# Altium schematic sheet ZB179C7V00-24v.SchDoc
size 1308 x 820 mm
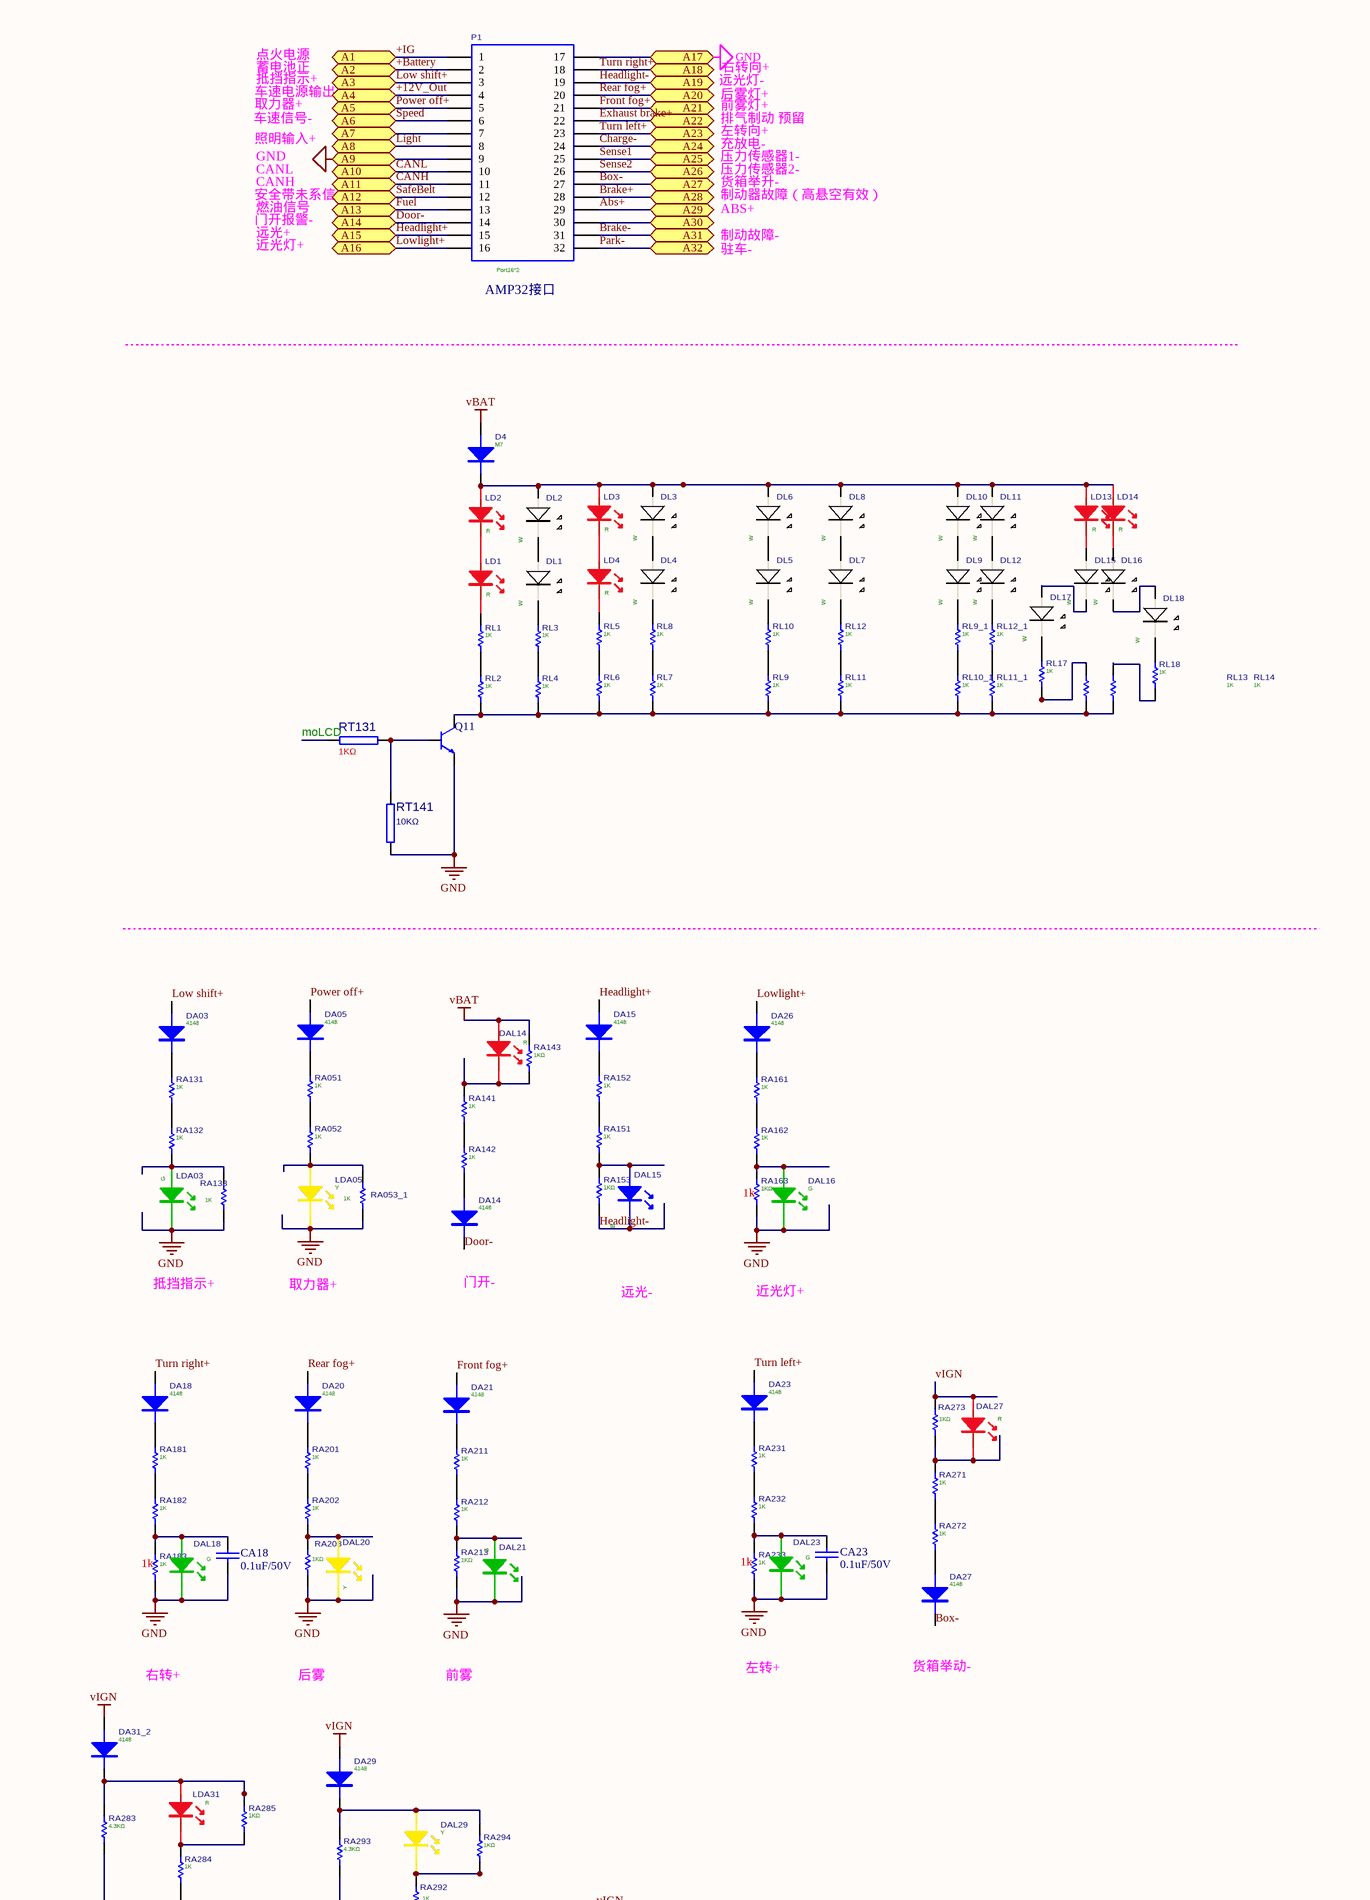
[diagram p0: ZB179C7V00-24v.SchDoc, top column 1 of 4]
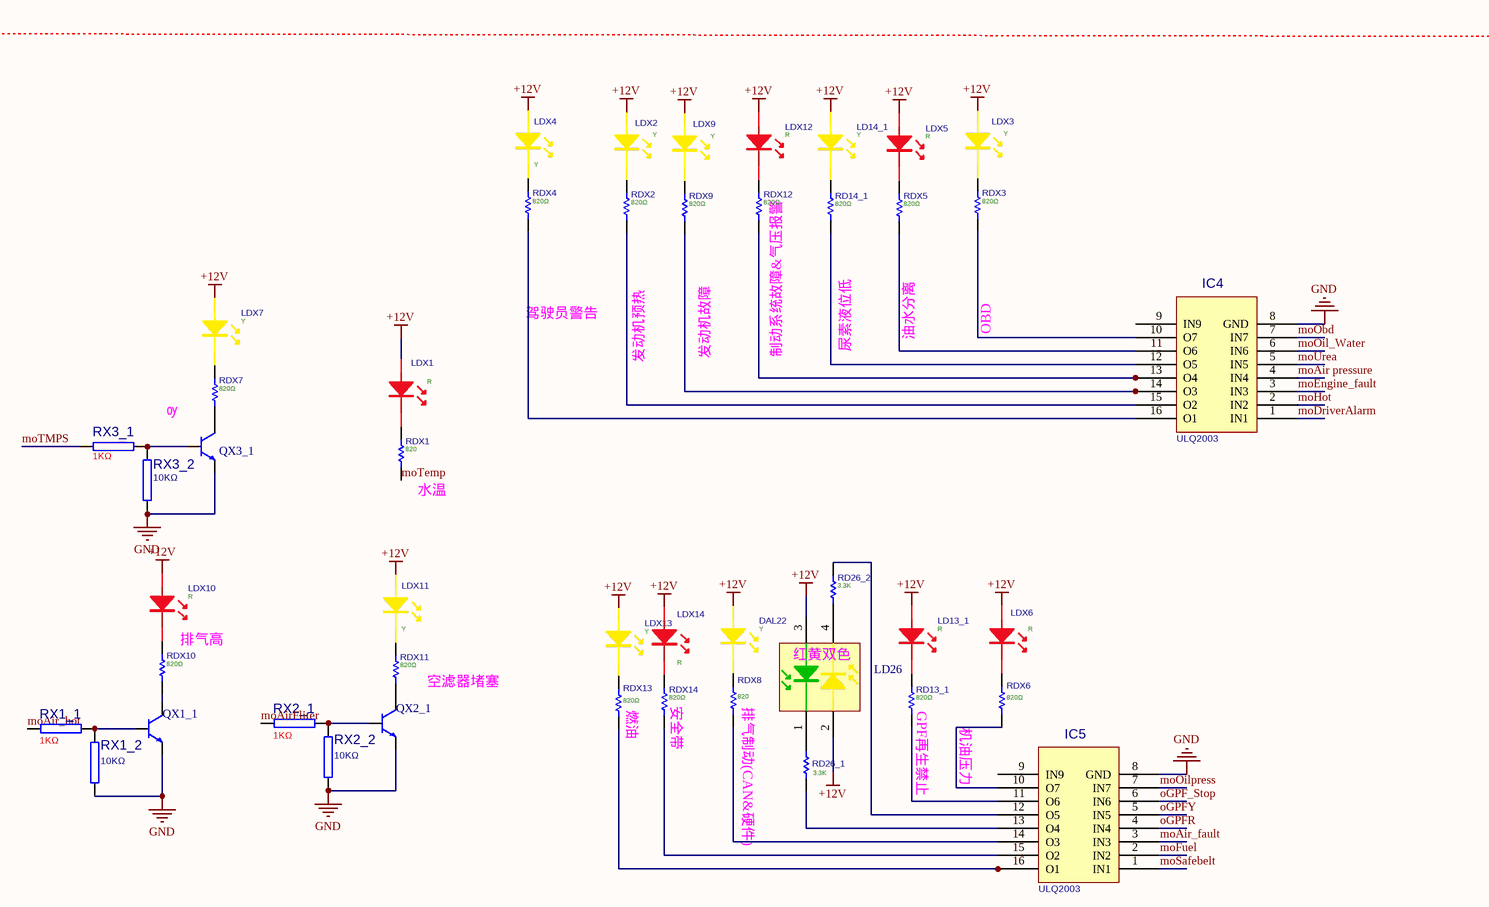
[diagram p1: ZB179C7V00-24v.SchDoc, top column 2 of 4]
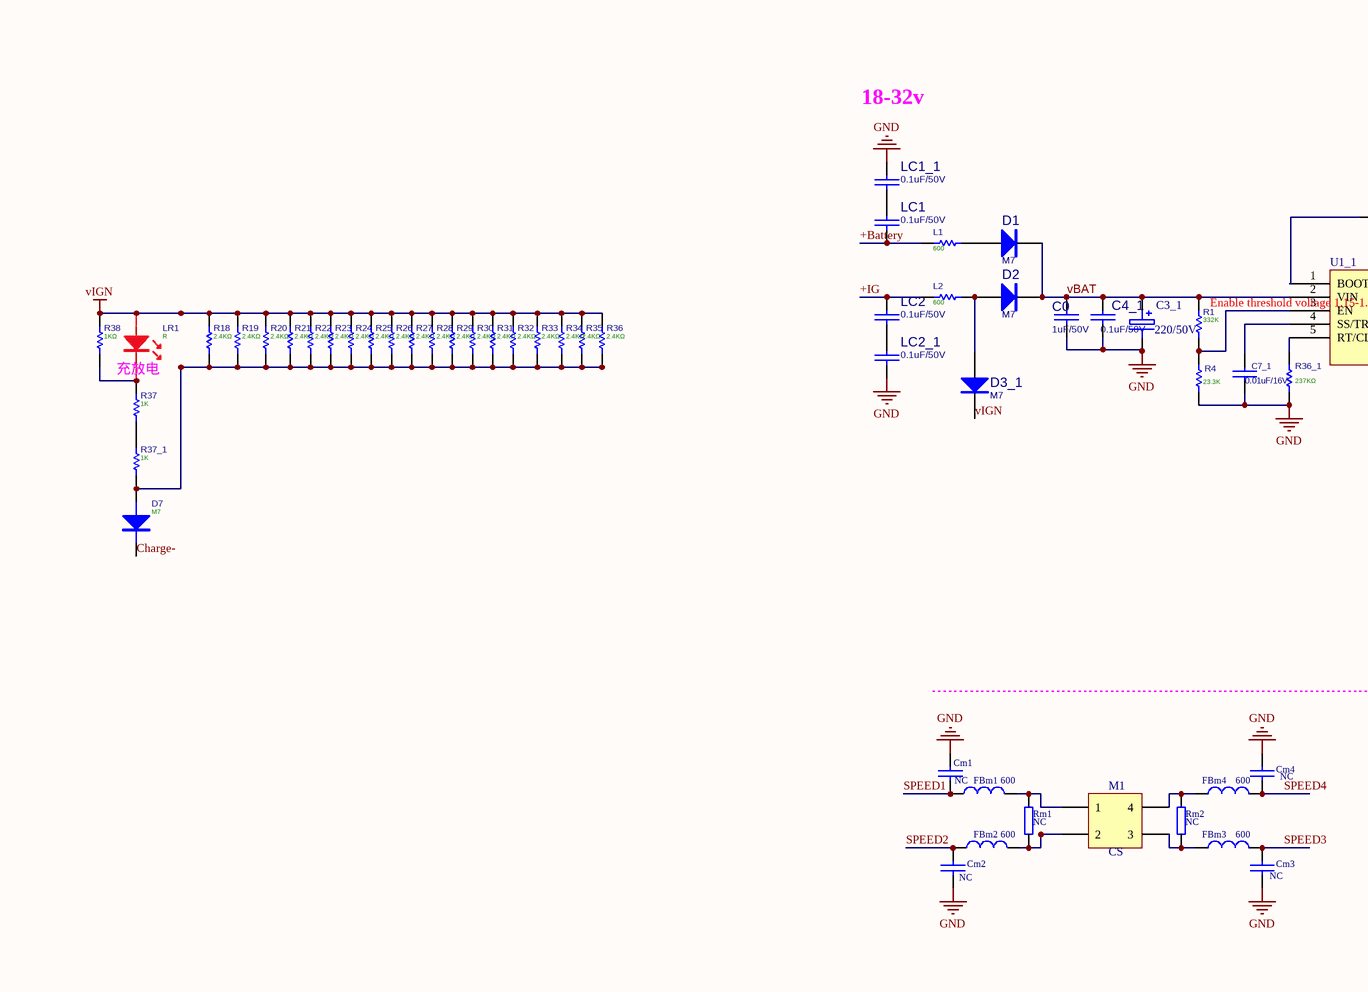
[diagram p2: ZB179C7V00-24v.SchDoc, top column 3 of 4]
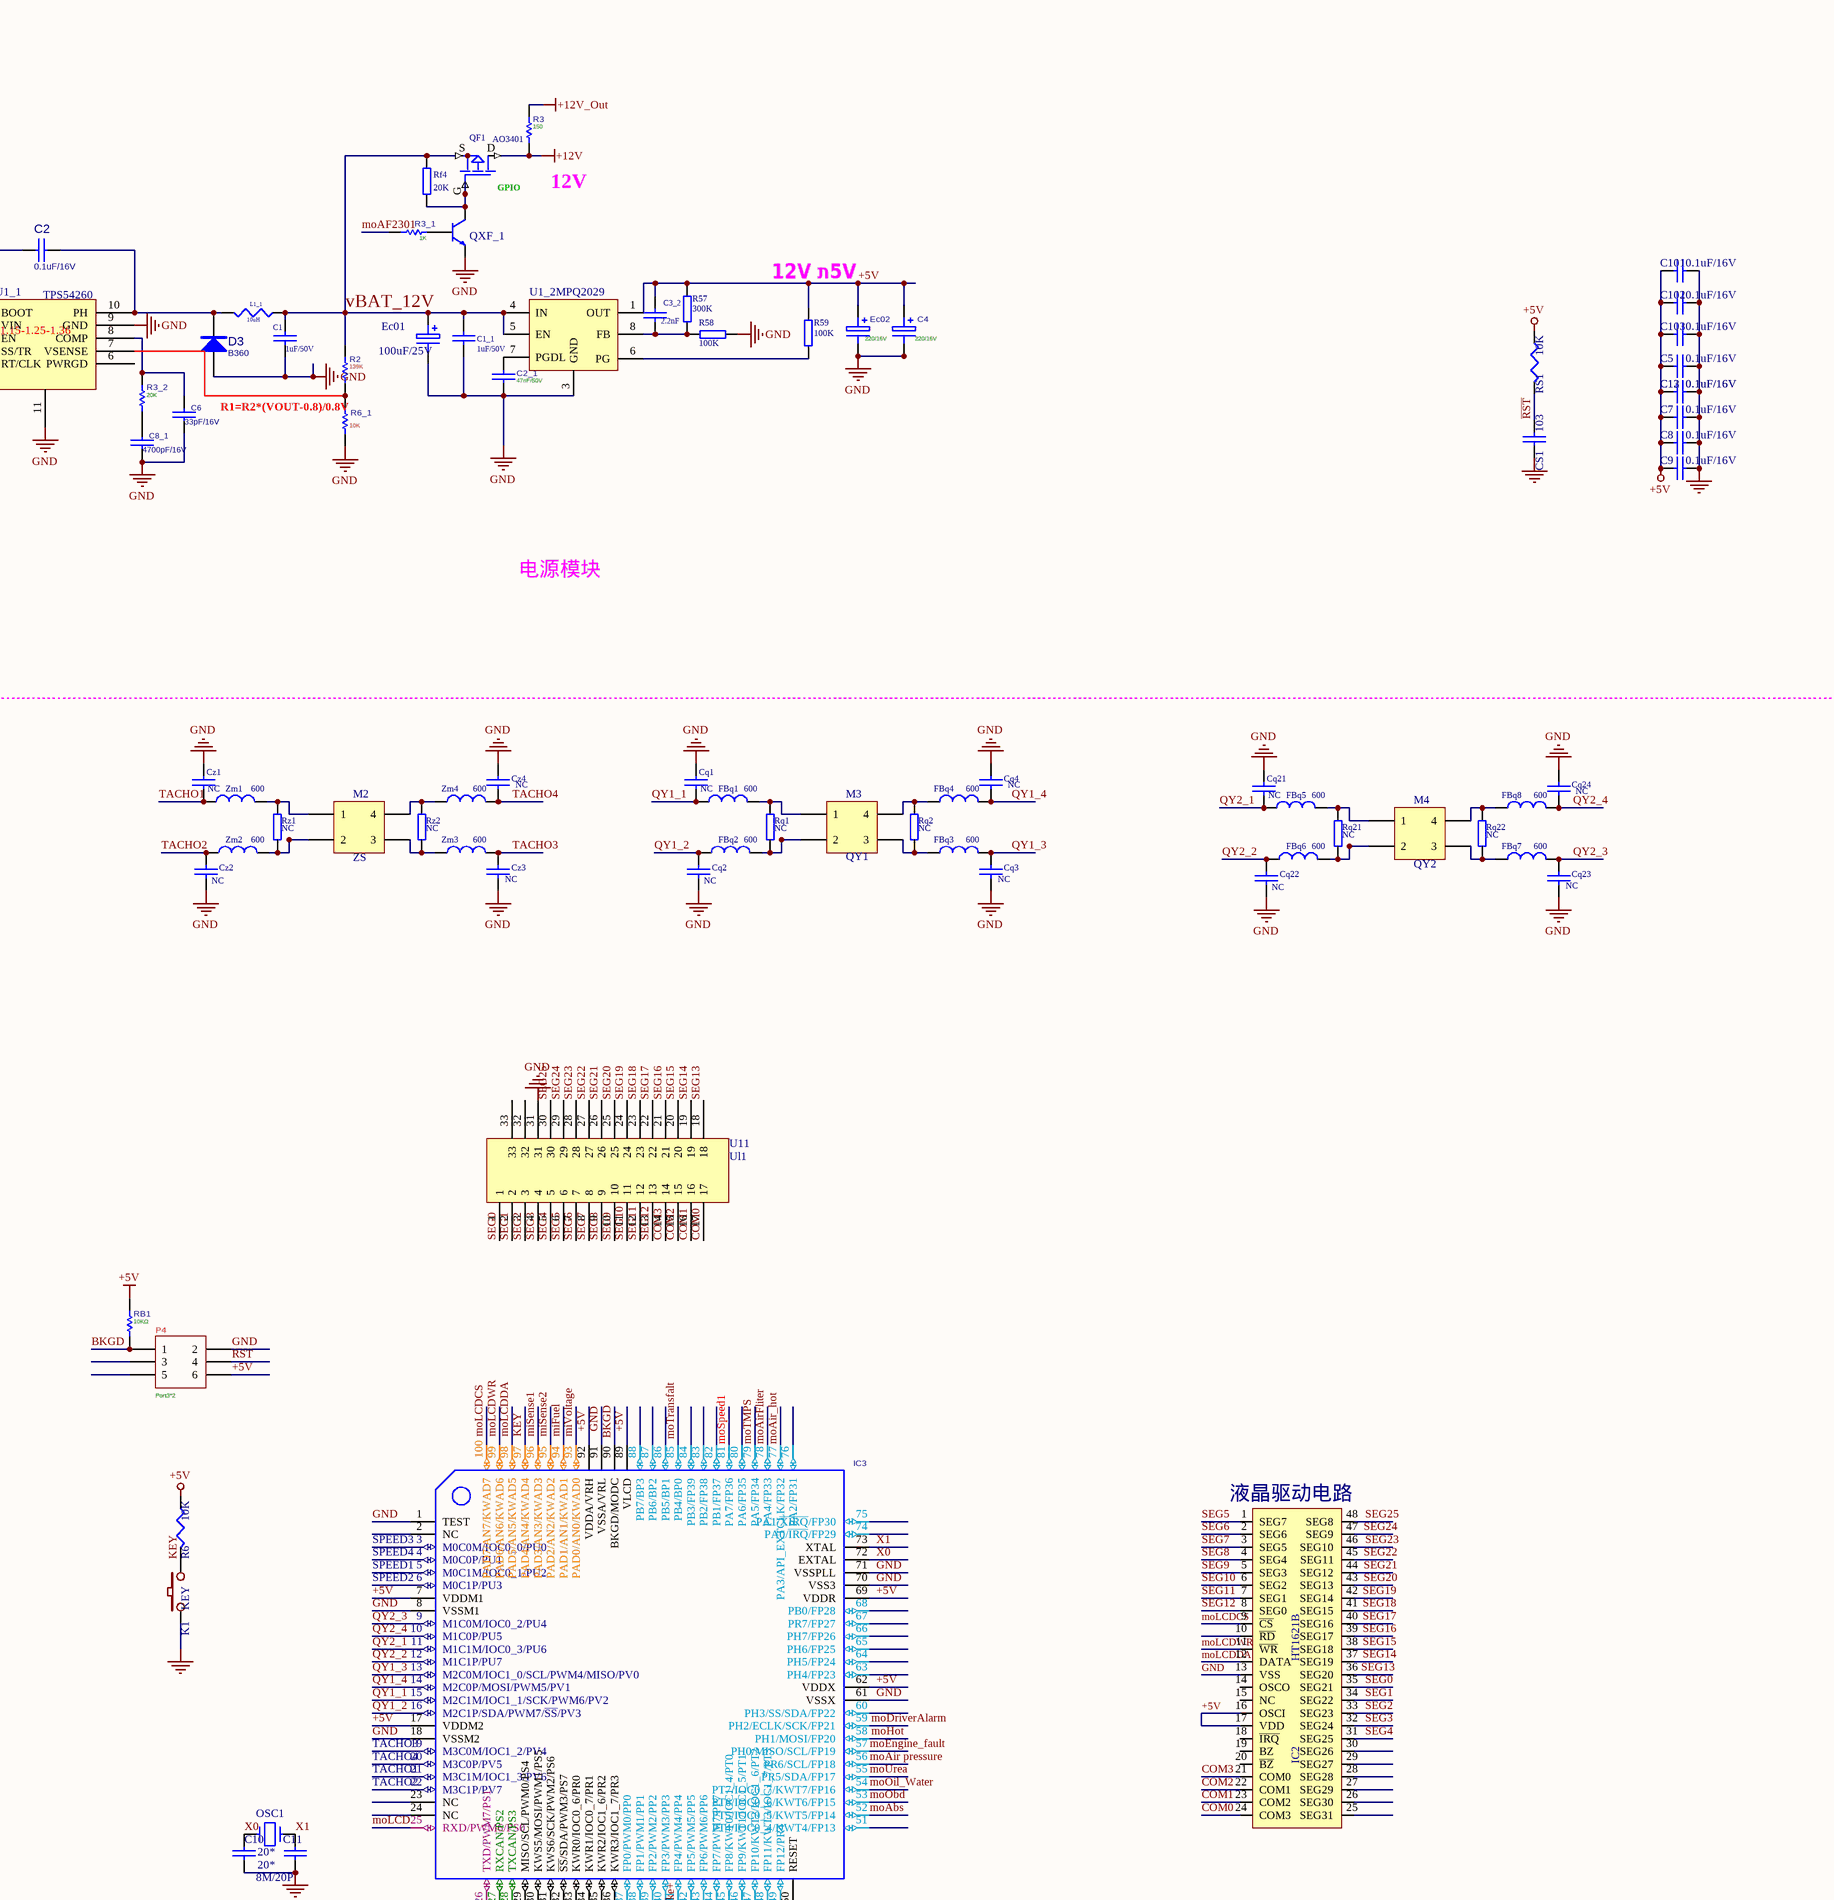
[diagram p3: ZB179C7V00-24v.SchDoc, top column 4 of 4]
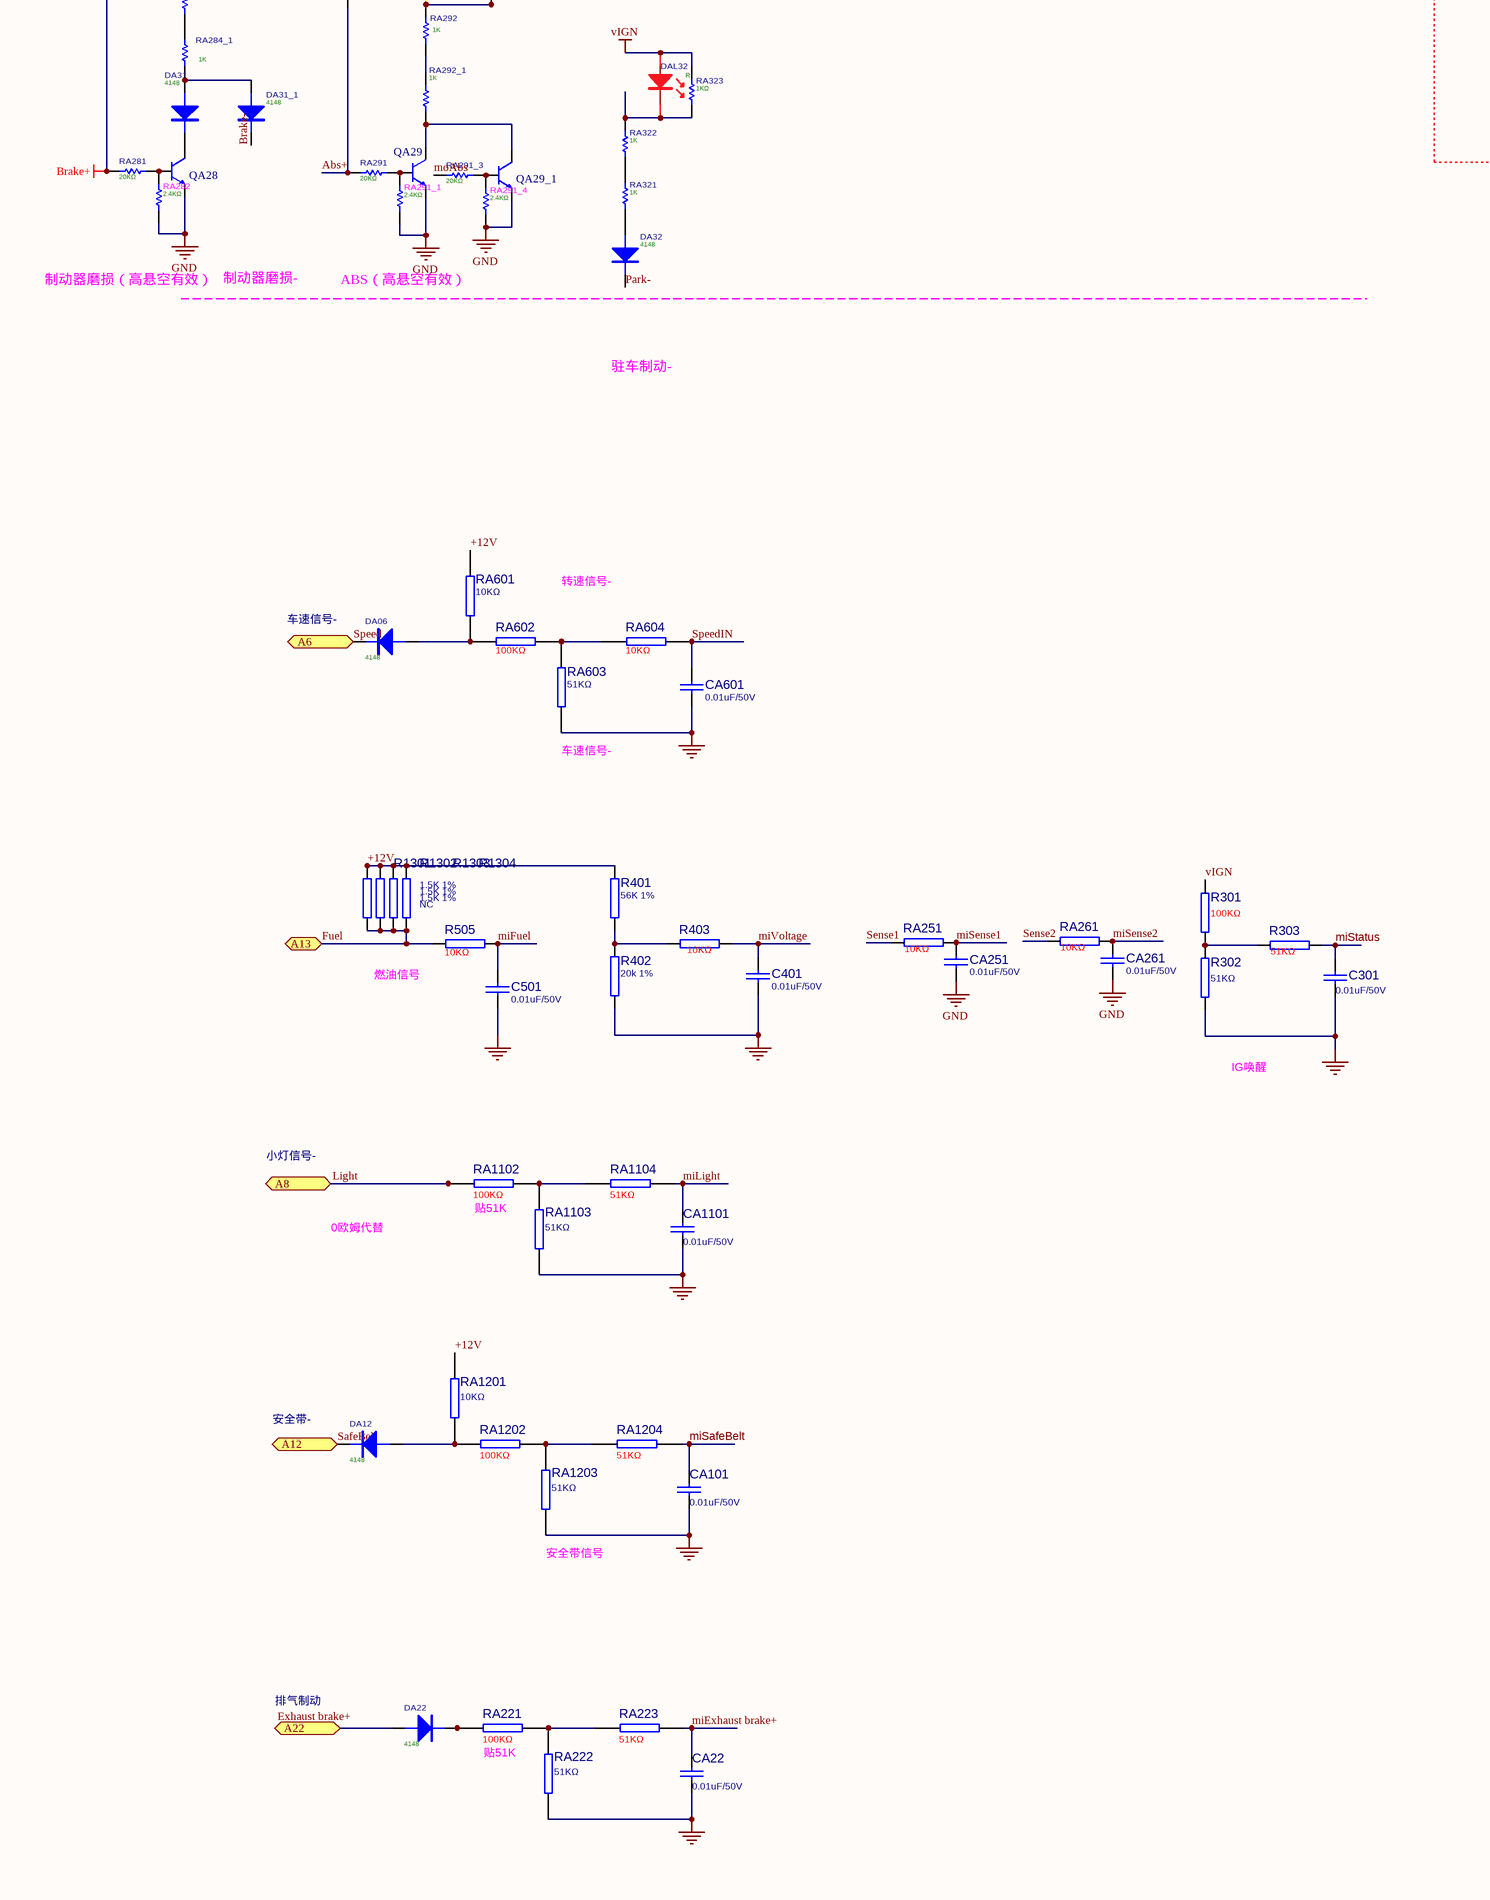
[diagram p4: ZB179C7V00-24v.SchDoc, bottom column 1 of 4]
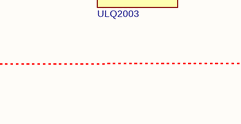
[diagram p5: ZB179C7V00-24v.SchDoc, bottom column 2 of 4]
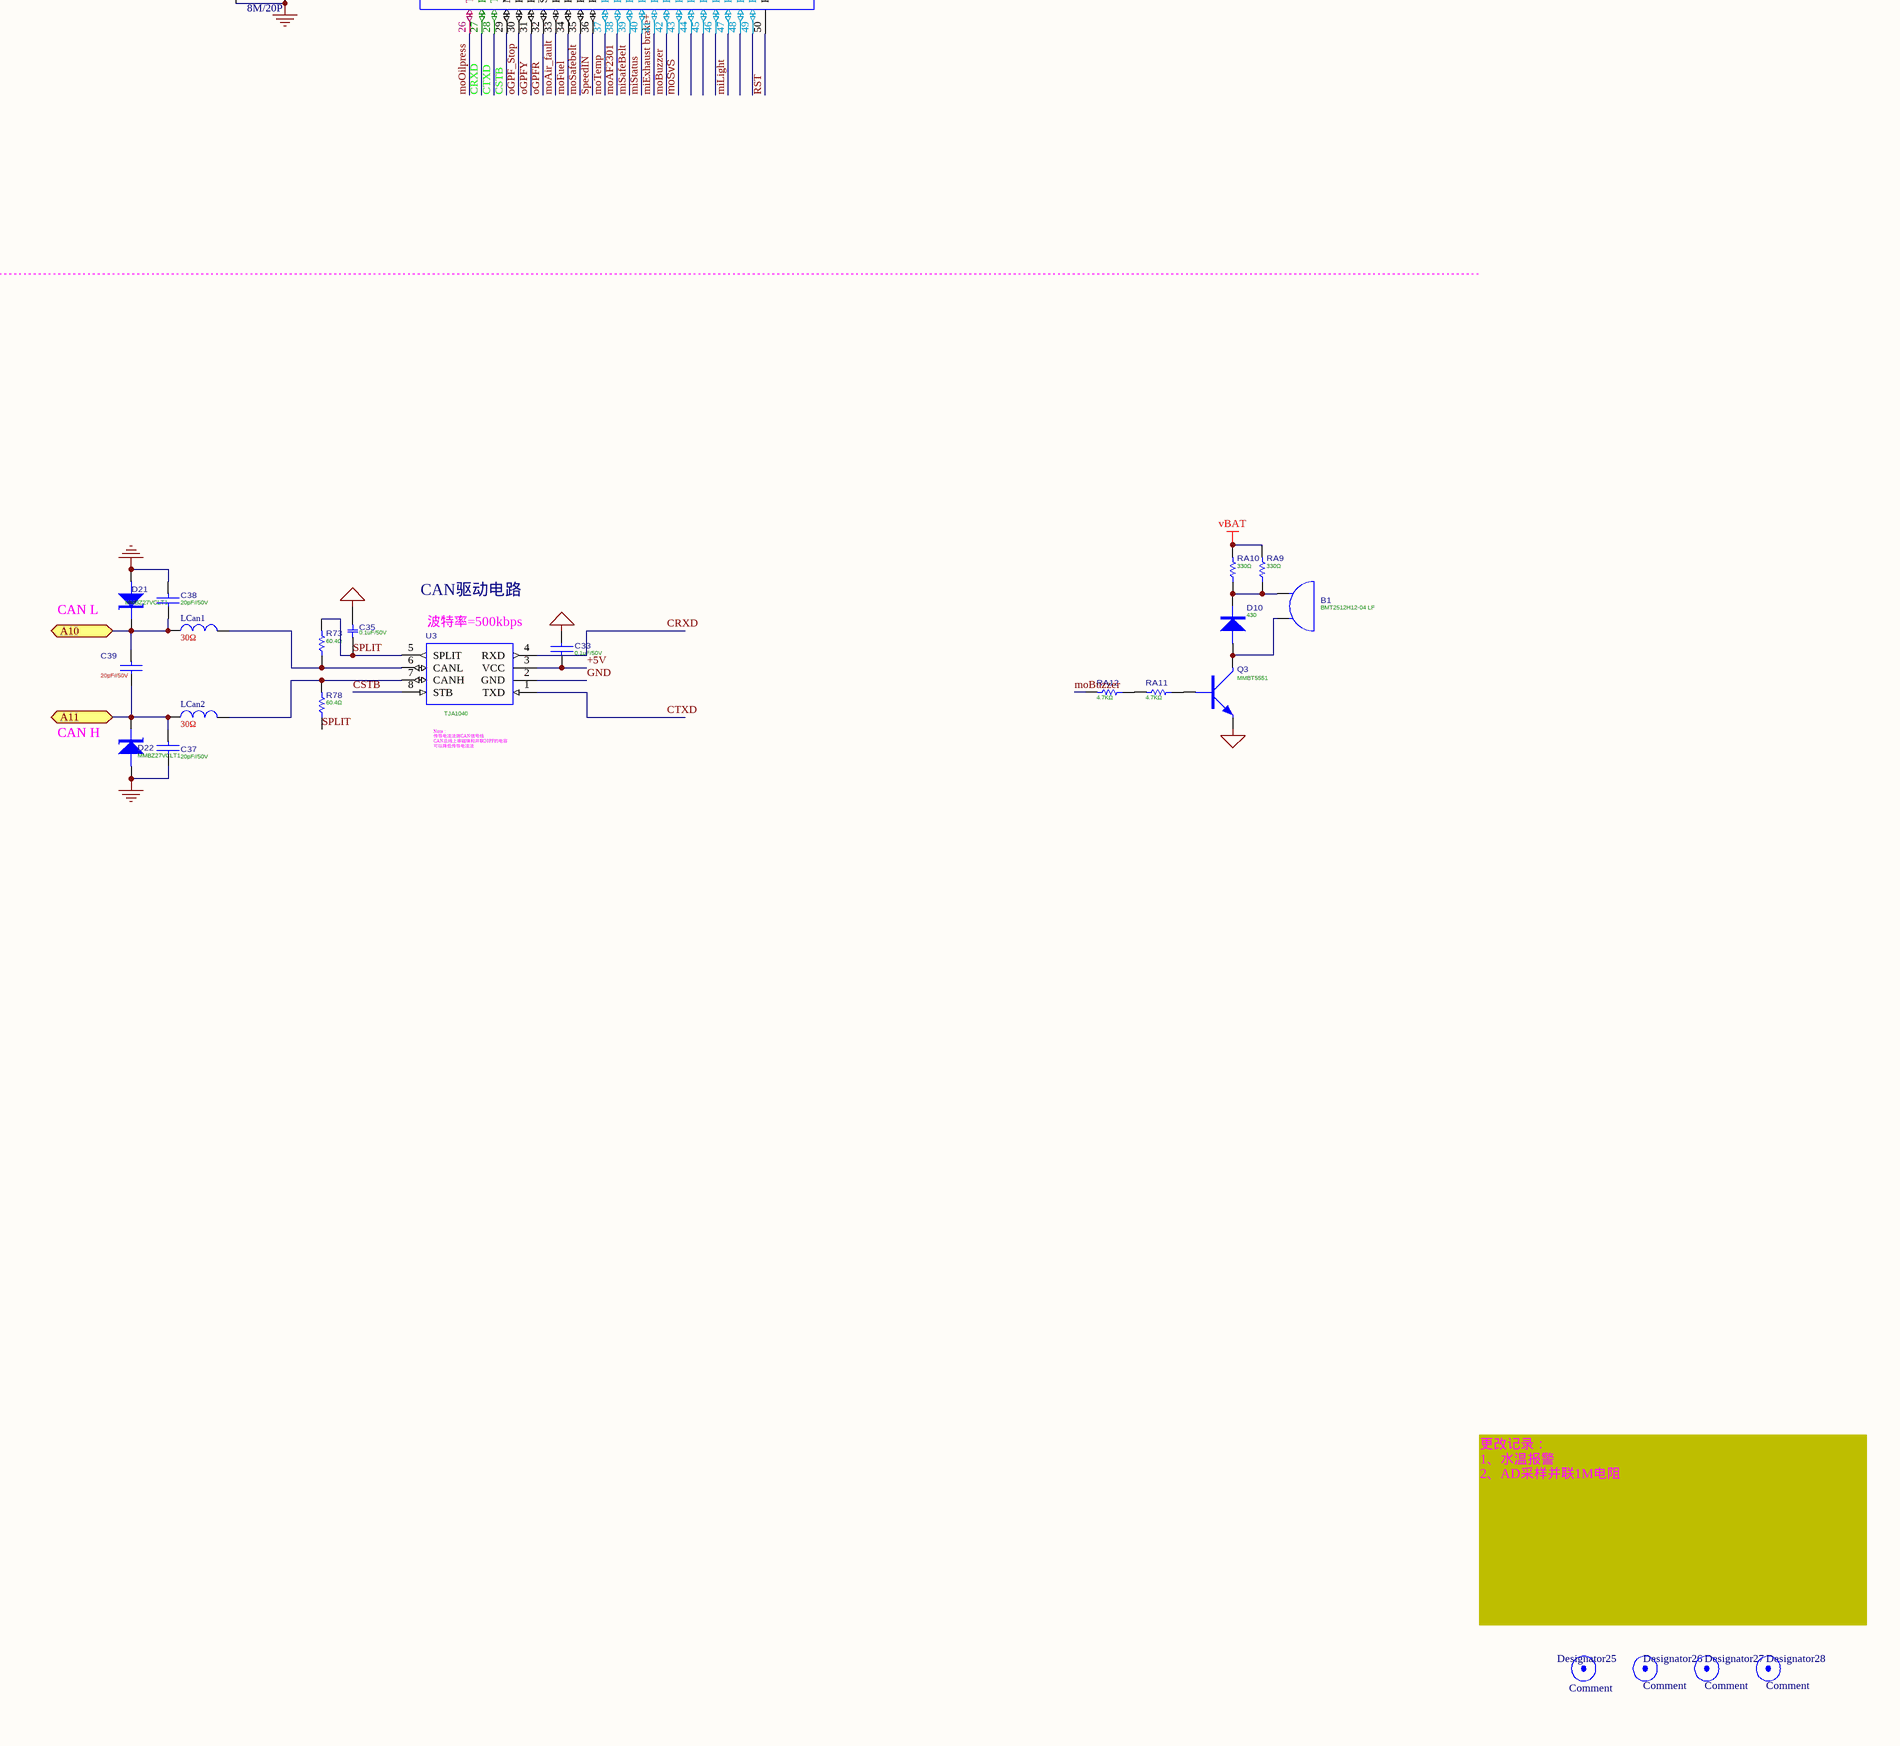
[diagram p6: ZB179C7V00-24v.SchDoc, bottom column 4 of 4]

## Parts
B1  BMT2512H12-04 LF  [AZ-2320E-P1]
C0  1uF/50V  [0805]
C1  1uF/50V  [0805]
C1_1  1uF/50V  [0603]
C2  0.1uF/16V  [0805]
C2_1  47nF/50V  [0603]
C3_1  220/50V  [VZH220/50V]
C3_2  2.2nF  [0603]
C4  220/16V  [VD220/16V]
C4_1  0.1uF/50V  [0805]
C5  0.1uF/16V  [0603]
C6  33pF/16V  [0603]
C7  0.1uF/16V  [0603]
C7_1  0.01uF/16V  [0603]
C8  0.1uF/16V  [0603]
C8_1  4700pF/16V  [0805]
C9  0.1uF/16V  [0603]
C10  20*  [0603]
C11  20*  [0603]
C12  0.1uF/16V  [0603]
C13  0.1uF/16V  [0603]
C33  0.1uF/50V  [0603]
C35  0.1uF/50V  [0603]
C37  20pF//50V  [0603]
C38  20pF//50V  [0603]
C39  20pF//50V  [0603]
C101  0.1uF/16V  [0603]
C102  0.1uF/16V  [0603]
C103  0.1uF/16V  [0603]
C301  0.01uF/50V  [0603]
C401  0.01uF/50V  [0603]
C501  0.01uF/50V  [0603]
CA18  0.1uF/50V  [0805]
CA22  0.01uF/50V  [0603]
CA23  0.1uF/50V  [0805]
CA101  0.01uF/50V  [0603]
CA251  0.01uF/50V  [0603]
CA261  0.01uF/50V  [0603]
CA601  0.01uF/50V  [C0603]
CA1101  0.01uF/50V  [0603]
Cm1  NC  [0603]
Cm2  NC  [0603]
Cm3  NC  [0603]
Cm4  NC  [0603]
Cq1  NC  [0603]
Cq2  NC  [0603]
Cq3  NC  [0603]
Cq4  NC  [0603]
Cq21  NC  [0603]
Cq22  NC  [0603]
Cq23  NC  [0603]
Cq24  NC  [0603]
CS1  103  [0603]
Cz1  NC  [0603]
Cz2  NC  [0603]
Cz3  NC  [0603]
Cz4  NC  [0603]
D1  M7  [7227]
D2  M7  [7227]
D3  B360  [7227]
D3_1  M7  [7227]
D4  M7  [7227]
D7  M7  [7227]
D10  430  [MiniMELF/SOD-80C]
D21  MMBZ27VCLT1  [SOT-23-BEC]
D22  MMBZ27VCLT1  [SOT-23-BEC]
DA03  4148  [MiniMELF/SOD-80C]
DA05  4148  [MiniMELF/SOD-80C]
DA06  4148  [MiniMELF/SOD-80C]
DA12  4148  [MiniMELF/SOD-80C]
DA14  4148  [MiniMELF/SOD-80C]
DA15  4148  [MiniMELF/SOD-80C]
DA18  4148  [MiniMELF/SOD-80C]
DA20  4148  [MiniMELF/SOD-80C]
DA21  4148  [MiniMELF/SOD-80C]
DA22  4148  [MiniMELF/SOD-80C]
DA23  4148  [MiniMELF/SOD-80C]
DA26  4148  [MiniMELF/SOD-80C]
DA27  4148  [MiniMELF/SOD-80C]
DA29  4148  [MiniMELF/SOD-80C]
DA31  4148  [MiniMELF/SOD-80C]
DA31_1  4148  [MiniMELF/SOD-80C]
DA31_2  4148  [MiniMELF/SOD-80C]
DA32  4148  [MiniMELF/SOD-80C]
DAL14  R  [LED3528]
DAL15  B  [LED3528]
DAL16  G  [LED3528]
DAL18  G  [LED3528]
DAL20  Y  [LED3528]
DAL21  G  [LED3528]
DAL22  Y  [LED3528]
DAL23  G  [LED3528]
DAL27  R  [LED3528]
DAL29  Y  [LED3528]
DAL32  R  [LED3528]
Designator25  Comment  [MARK]
Designator26  Comment  [MARK]
Designator27  Comment  [MARK]
Designator28  Comment  [MARK]
DL1  W  [LED3528]
DL2  W  [LED3528]
DL3  W  [LED3528]
DL4  W  [LED3528]
DL5  W  [LED3528]
DL6  W  [LED3528]
DL7  W  [LED3528]
DL8  W  [LED3528]
DL9  W  [LED3528]
DL10  W  [LED3528]
DL11  W  [LED3528]
DL12  W  [LED3528]
DL15  W  [LED3528]
DL16  W  [LED3528]
DL17  W  [LED3528]
DL18  W  [LED3528]
Ec01  100uF/25V  [4E220/16H]
Ec02  220/16V  [VD220/16V]
FBm1  600  [0603]
FBm2  600  [0603]
FBm3  600  [0603]
FBm4  600  [0603]
FBq1  600  [0603]
FBq2  600  [0603]
FBq3  600  [0603]
FBq4  600  [0603]
FBq5  600  [0603]
FBq6  600  [0603]
FBq7  600  [0603]
FBq8  600  [0603]
IC2  HT1621B  [SSO-48]
IC3  MC9S12HY48MLL  [TQFP-100-0.5]  (value not drawn)
IC4  ULQ2003  [SO-16]
IC5  ULQ2003  [SO-16]
K1  KEY  [K1]
L1  600  [0805]
L1_1  10uH  [SPM6530T-100M]
L2  600  [0805]
LC1  0.1uF/50V  [0805]
LC1_1  0.1uF/50V  [0805]
LC2  0.1uF/50V  [0805]
LC2_1  0.1uF/50V  [0805]
LCan1  30Ω  [0603]
LCan2  30Ω  [0603]
LD1  R  [LED3528]
LD2  R  [LED3528]
LD3  R  [LED3528]
LD4  R  [LED3528]
LD13  R  [LED3528]
LD13_1  R  [LED3528]
LD14  R  [LED3528]
LD14_1  Y  [LED3528]
LD26  Y/G  [67-22]  (value not drawn)
LDA03  G  [LED3528]
LDA05  Y  [LED3528]
LDA31  R  [LED3528]
LDX1  R  [LED3528]
LDX2  Y  [LED3528]
LDX3  Y  [LED3528]
LDX4  Y  [LED3528]
LDX5  R  [LED3528]
LDX6  R  [LED3528]
LDX7  Y  [LED3528]
LDX9  Y  [LED3528]
LDX10  R  [LED3528]
LDX11  Y  [LED3528]
LDX12  R  [LED3528]
LDX13  Y  [LED3528]
LDX14  R  [LED3528]
LR1  R  [LED3528]
M1  CS  [M]
M2  ZS  [M]
M3  QY1  [M]
M4  QY2  [M]
OSC1  8M/20P  [HC-49S]
P1  Port16*2  [AMP-32-B]
P4  Port3*2  [SIP-6]
Q3  MMBT5551  [SOT-23-BEC]
Q11  5551  [SOT-23-BEC]  (value not drawn)
QA28  5551  [SOT-23-BEC]  (value not drawn)
QA29  5551  [SOT-23-BEC]  (value not drawn)
QA29_1  5551  [SOT-23-BEC]  (value not drawn)
QF1  AO3401  [SOT-23-GSD]
QX1_1  5551  [SOT-23-BEC]  (value not drawn)
QX2_1  5551  [SOT-23-BEC]  (value not drawn)
QX3_1  5551  [SOT-23-BEC]  (value not drawn)
QXF_1  5551  [SOT-23-BEC]  (value not drawn)
R1  332K  [0603]
R2  139K  [1206]
R3  150  [1206]
R3_1  1K  [0603]
R3_2  20K  [0603]
R4  23.3K  [0603]
R6  10K  [0603]
R6_1  10K  [1206]
R18  2.4KΩ  [1206]
R19  2.4KΩ  [1206]
R20  2.4KΩ  [1206]
R21  2.4KΩ  [1206]
R22  2.4KΩ  [1206]
R23  2.4KΩ  [1206]
R24  2.4KΩ  [1206]
R25  2.4KΩ  [1206]
R26  2.4KΩ  [1206]
R27  2.4KΩ  [1206]
R28  2.4KΩ  [1206]
R29  2.4KΩ  [1206]
R30  2.4KΩ  [1206]
R31  2.4KΩ  [1206]
R32  2.4KΩ  [1206]
R33  2.4KΩ  [1206]
R34  2.4KΩ  [1206]
R35  2.4KΩ  [1206]
R36  2.4KΩ  [1206]
R36_1  237KΩ  [0603]
R37  1K  [1206]
R37_1  1K  [1206]
R38  1KΩ  [0603]
R57  300K  [0603]
R58  100K  [0603]
R59  100K  [0603]
R73  60.4Ω  [1206]
R78  60.4Ω  [1206]
R301  100KΩ  [0603]
R302  51KΩ  [0603]
R303  51KΩ  [0603]
R401  56K 1%  [0805]
R402  20k 1%  [0805]
R403  10KΩ  [0805]
R505  10KΩ  [1206]
R1301  1.5K 1%  [1206]
R1302  1.5K 1%  [1206]
R1303  NC  [1206]
R1304  1.5K 1%  [1206]
RA9  330Ω  [1206]
RA10  330Ω  [1206]
RA11  4.7KΩ  [0603]
RA12  4.7KΩ  [0603]
RA051  1K  [1206]
RA052  1K  [1206]
RA053_1  1K  [0805]
RA131  1K  [1206]
RA132  1K  [1206]
RA133  1K  [0805]
RA141  1K  [1206]
RA142  1K  [1206]
RA143  1KΩ  [0805]
RA151  1K  [1206]
RA152  1K  [1206]
RA153  1KΩ  [0805]
RA161  1K  [1206]
RA162  1K  [1206]
RA163  1KΩ  [0805]
RA181  1K  [1206]
RA182  1K  [1206]
RA183  1K  [0805]
RA201  1K  [1206]
RA202  1K  [1206]
RA203  1KΩ  [0805]
RA211  1K  [1206]
RA212  1K  [1206]
RA213  1KΩ  [0805]
RA221  100KΩ  [0805]
RA222  51KΩ  [0805]
RA223  51KΩ  [0805]
RA231  1K  [1206]
RA232  1K  [1206]
RA233  1K  [0805]
RA251  10KΩ  [0805]
RA261  10KΩ  [0805]
RA271  1K  [1206]
RA272  1K  [1206]
RA273  1KΩ  [0805]
RA281  20KΩ  [0603]
RA282  2.4KΩ  [0603]
RA283  4.3KΩ  [0603]
RA284  1K  [1206]
RA284_1  1K  [1206]
RA285  1KΩ  [0805]
RA291  20KΩ  [0603]
RA291_1  2.4KΩ  [0603]
RA291_3  20KΩ  [0603]
RA291_4  2.4KΩ  [0603]
RA292  1K  [1206]
RA292_1  1K  [1206]
RA293  4.3KΩ  [0805]
RA294  1KΩ  [0805]
RA321  1K  [1206]
RA322  1K  [1206]
RA323  1KΩ  [0805]
RA601  10KΩ  [0805]
RA602  100KΩ  [0805]
RA603  51KΩ  [0805]
RA604  10KΩ  [0805]
RA1102  100KΩ  [0603]
RA1103  51KΩ  [0603]
RA1104  51KΩ  [0603]
RA1201  10KΩ  [0805]
RA1202  100KΩ  [0805]
RA1203  51KΩ  [0805]
RA1204  51KΩ  [0805]
RB1  10KΩ  [0603]
RD13_1  820Ω  [1206]
RD14_1  820Ω  [1206]
RD26_1  3.3K  [1206]
RD26_2  3.3K  [1206]
RDX1  820  [1206]
RDX2  820Ω  [1206]
RDX3  820Ω  [1206]
RDX4  820Ω  [1206]
RDX5  820Ω  [1206]
RDX6  820Ω  [1206]
RDX7  820Ω  [1206]
RDX8  820  [1206]
RDX9  820Ω  [1206]
RDX10  820Ω  [1206]
RDX11  820Ω  [1206]
RDX12  820Ω  [1206]
RDX13  820Ω  [1206]
RDX14  820Ω  [1206]
Rf4  20K  [0603]
RL1  1K  [1206]
RL2  1K  [1206]
RL3  1K  [1206]
RL4  1K  [1206]
RL5  1K  [1206]
RL6  1K  [1206]
RL7  1K  [1206]
RL8  1K  [1206]
RL9  1K  [1206]
RL9_1  1K  [1206]
RL10  1K  [1206]
RL10_1  1K  [1206]
RL11  1K  [1206]
RL11_1  1K  [1206]
RL12  1K  [1206]
RL12_1  1K  [1206]
RL13  1K  [1206]
RL14  1K  [1206]
RL17  1K  [1206]
RL18  1K  [1206]
Rm1  NC  [0603]
Rm2  NC  [0603]
Rq1  NC  [0603]
Rq2  NC  [0603]
Rq21  NC  [0603]
Rq22  NC  [0603]
RS1  10K  [0603]
RT131  1KΩ  [0603]
RT141  10KΩ  [0603]
RX1_1  1KΩ  [0603]
RX1_2  10KΩ  [0603]
RX2_1  1KΩ  [0603]
RX2_2  10KΩ  [0603]
RX3_1  1KΩ  [0603]
RX3_2  10KΩ  [0603]
Rz1  NC  [0603]
Rz2  NC  [0603]
U1_1  TPS54260  [MSOP]
U1_2  MPQ2029  [SOIC8]
U3  TJA1040  [SO-8]
U11  Ul1  [LCD]
Zm1  600  [0603]
Zm2  600  [0603]
Zm3  600  [0603]
Zm4  600  [0603]

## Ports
A1, A2, A3, A4, A5, A6, A7, A8, A9, A10, A11, A12, A13, A14, A15, A16, A17, A18, A19, A20, A21, A22, A23, A24, A25, A26, A27, A28, A29, A30, A31, A32

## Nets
+5V: C3_2.1 C4.+ C5.2 C7.2 C8.2 C9.2 C12.2 C13.2 C33.1 C101.2 C102.2 C103.2 Ec02.+ IC2.16(OSCI) IC2.17(VDD) IC3.7(VDDM1) IC3.17(VDDM2) IC3.62(VDDX) IC3.69(VDDR) IC3.89(VLCD) IC3.92(VDDA/VRH) P4.6 R6.2 R57.2 R59.2 RB1.2 RS1.2 U1_2.1(OUT) U3.3(VCC)
+12V: DAL22.1 LD13_1.1 LD14_1.1 LD26.2 LD26.3 LDX1.1 LDX2.1 LDX3.1 LDX4.1 LDX5.1 LDX6.1 LDX7.1 LDX9.1 LDX10.1 LDX11.1 LDX12.1 LDX13.1 LDX14.1 QF1.D R3.1 R401.2 R1301.2 R1302.2 R1303.2 R1304.2 RA601.1 RA1201.2
+12V_Out: P1.4 R3.2 ; port A4
Brake+: P1.28 RA281.1 RA283.1 ; port A28
GND: C0.2 C1.2 C1_1.2 C2_1.1 C3_1.- C4.- C4_1.2 C5.1 C6.1 C7.1 C7_1.1 C8.1 C8_1.1 C9.1 C10.2 C11.2 C12.1 C13.1 C33.2 C35.2 C37.2 C38.1 C101.1 C102.1 C103.1 C301.1 C401.2 C501.2 CA18.2 CA22.2 CA23.2 CA101.2 CA251.2 CA261.2 CA601.1 CA1101.2 Cm1.1 Cm2.2 Cm3.2 Cm4.1 Cq1.1 Cq2.2 Cq3.2 Cq4.1 Cq21.1 Cq22.2 Cq23.2 Cq24.1 CS1.1 Cz1.1 Cz2.2 Cz3.2 Cz4.1 D3.1 D21.1 D22.1 DAL16.2 DAL18.2 DAL20.2 DAL21.2 DAL23.2 Ec01.2 Ec02.- IC2.13(VSS) IC3.1(TEST) IC3.8(VSSM1) IC3.18(VSSM2) IC3.61(VSSX) IC3.70(VSS3) IC3.71(VSSPLL) IC3.91(VSSA/VRL) IC4.8(GND) IC5.8(GND) K1.1 LC1_1.1 LC2_1.2 LDA03.2 LDA05.2 P1.9 P1.17 P4.2 Q3.E Q11.E QA28.E QA29.E QA29_1.E QX1_1.E QX2_1.E QX3_1.E QXF_1.E R4.1 R6_1.1 R36_1.1 R58.2 R302.2 R402.2 RA053_1.2 RA133.2 RA163.1 RA183.1 RA203.2 RA213.2 RA222.1 RA233.1 RA282.1 RA291_1.1 RA291_4.1 RA603.2 RA1103.1 RA1203.1 RT141.2 RX1_2.2 RX2_2.2 RX3_2.2 U1_1.9(GND) U1_1.11 U1_2.3(GND) U3.2(GND) U11.31 ; port A9, port A17
vBAT: C0.1 C3_1.+ C4_1.1 D1.2 D2.2 D4.1 DAL14.1 R1.2 RA9.2 RA10.2 RA143.2 U1_1.2(VIN)
vIGN: D3_1.2 DA29.1 DA31_2.1 DAL27.1 DAL32.1 LR1.1 R18.2 R19.2 R20.2 R21.2 R22.2 R23.2 R24.2 R25.2 R26.2 R27.2 R28.2 R29.2 R30.2 R31.2 R32.2 R33.2 R34.2 R35.2 R36.2 R38.2 R301.1 RA273.1 RA323.2
+Battery: L1.2 LC1.2 P1.2 ; port A2
+IG: L2.2 LC2.1 P1.1 ; port A1
A7: P1.7 ; port A7
A30: P1.30 ; port A30
Abs+: P1.29 RA291.1 RA293.1 ; port A29
BKGD: IC3.90(BKGD/MODC) P4.1 RB1.1
Box-: DA27.2 P1.27 ; port A27
Brake-: DA31_1.2 P1.31 ; port A31
CANH: C37.1 C39.2 D22.2 LCan2.2 P1.11 ; port A11
CANL: C38.2 C39.1 D21.2 LCan1.2 P1.10 ; port A10
Charge-: D7.2 P1.24 ; port A24
COM0: IC2.24(COM3) U11.17
COM1: IC2.23(COM2) U11.16
COM2: IC2.22(COM1) U11.15
COM3: IC2.21(COM0) U11.14
CRXD: IC3.27(RXCAN/PS2) U3.4(RXD)
CSTB: IC3.29(MISO/SCL/PWM0/PS4) U3.8(STB)
CTXD: IC3.28(TXCAN/PS3) U3.1(TXD)
Door-: DA14.2 P1.14 ; port A14
Exhaust brake+: DA22.1 P1.22 ; port A22
Front fog+: DA21.1 P1.21 ; port A21
Fuel: P1.13 R505.2 R1301.1 R1302.1 R1303.1 R1304.1 ; port A13
Headlight+: DA15.1 P1.15 ; port A15
Headlight-: DAL15.2 P1.19 RA153.2 ; port A19
KEY: IC3.97(PAD4/AN4/KWAD4) K1.2 R6.1
Light: P1.8 RA1102.2 ; port A8
Low shift+: DA03.1 P1.3 ; port A3
Lowlight+: DA26.1 P1.16 ; port A16
miExhaust brake+: CA22.1 IC3.41(FP4/PWM4/PP4) RA223.2
miFuel: C501.1 IC3.94(PAD1/AN1/KWAD1) R505.1
miLight: CA1101.1 IC3.47(FP10/KWT2/IOC1_6/PT2) RA1104.2
miSafeBelt: CA101.1 IC3.39(FP2/PWM2/PP2) RA1204.2
miSense1: CA251.1 IC3.96(PAD3/AN3/KWAD3) RA251.1
miSense2: CA261.1 IC3.95(PAD2/AN2/KWAD2) RA261.1
miStatus: C301.2 IC3.40(FP3/PWM3/PP3) R303.1
miVoltage: C401.1 IC3.93(PAD0/AN0/KWAD0) R403.1
moAbs: IC3.52(PT5/IOC0_5/KWT5/FP14) RA291_3.1
moAF2301: IC3.38(FP1/PWM1/PP1) R3_1.2
moAir pressure: IC3.56(PR6/SCL/FP18) IC4.4(IN4)
moAir_fault: IC3.33(KWR0/IOC0_6/PR0) IC5.3(IN3)
moAir_hot: IC3.77(PA3/API_EXTCLK/FP32) RX1_1.1
moAirFliter: IC3.78(PA4/FP33) RX2_1.1
moBuzzer: IC3.42(FP5/PWM5/PP5) RA12.2
moDriverAlarm: IC3.59(PH2/ECLK/SCK/FP21) IC4.1(IN1)
moEngine_fault: IC3.57(PH0/MISO/SCL/FP19) IC4.3(IN3)
moFuel: IC3.34(KWR1/IOC0_7/PR1) IC5.2(IN2)
moHot: IC3.58(PH1/MOSI/FP20) IC4.2(IN2)
moLCD: IC3.25(RXD/PWM6/PS0) RT131.1
moLCDCS: IC2.9(~{CS}) IC3.100(PAD7/AN7/KWAD7)
moLCDDA: IC2.12(DATA) IC3.98(PAD5/AN5/KWAD5)
moLCDWR: IC2.11(~{WR}) IC3.99(PAD6/AN6/KWAD6)
moObd: IC3.53(PT6/IOC0_6/KWT6/FP15) IC4.7(IN7)
moOil_Water: IC3.54(PT7/IOC0_7/KWT7/FP16) IC4.6(IN6)
moOilpress: IC3.26(TXD/PWM7/PS1) IC5.7(IN7)
moSafebelt: IC3.35(KWR2/IOC1_6/PR2) IC5.1(IN1)
moSpeed1: IC3.81(PA7/FP36)
moSvS: IC3.43(FP6/PWM6/PP6)
moTemp: IC3.37(FP0/PWM0/PP0) RDX1.2
moTMPS: IC3.79(PA5/FP34) RX3_1.1
moTransfalt: IC3.85(PB4/BP0)
moUrea: IC3.55(PR5/SDA/FP17) IC4.5(IN5)
oGPF_Stop: IC3.30(KWS5/MOSI/PWM1/PS5) IC5.6(IN6)
oGPFR: IC3.32(~{SS}/SDA/PWM3/PS7) IC5.4(IN4)
oGPFY: IC3.31(KWS6/SCK/PWM2/PS6) IC5.5(IN5)
Park-: DA32.2 P1.32 ; port A32
Power off+: DA05.1 P1.5 ; port A5
QY1_1: Cq1.2 FBq1.1 IC3.15(M2C1M/IOC1_1/SCK/PWM6/PV2)
QY1_2: Cq2.1 FBq2.1 IC3.16(M2C1P/SDA/PWM7/~{SS}/PV3)
QY1_3: Cq3.1 FBq3.2 IC3.13(M2C0M/IOC1_0/SCL/PWM4/MISO/PV0)
QY1_4: Cq4.2 FBq4.2 IC3.14(M2C0P/MOSI/PWM5/PV1)
QY2_1: Cq21.2 FBq5.1 IC3.11(M1C1M/IOC0_3/PU6)
QY2_2: Cq22.1 FBq6.1 IC3.12(M1C1P/PU7)
QY2_3: Cq23.1 FBq7.2 IC3.9(M1C0M/IOC0_2/PU4)
QY2_4: Cq24.2 FBq8.2 IC3.10(M1C0P/PU5)
~{RST}: CS1.2 IC3.50(RESET) P4.4 RS1.1
Rear fog+: DA20.1 P1.20 ; port A20
SafeBelt: DA12.2 P1.12 ; port A12
SEG0: IC2.35(SEG21) U11.1
SEG1: IC2.34(SEG22) U11.2
SEG2: IC2.33(SEG23) U11.3
SEG3: IC2.32(SEG24) U11.4
SEG4: IC2.31(SEG25) U11.5
SEG5: IC2.1(SEG7) U11.6
SEG6: IC2.2(SEG6) U11.7
SEG7: IC2.3(SEG5) U11.8
SEG8: IC2.4(SEG4) U11.9
SEG9: IC2.5(SEG3) U11.10
SEG10: IC2.6(SEG2) U11.11
SEG11: IC2.7(SEG1) U11.12
SEG12: IC2.8(SEG0) U11.13
SEG13: IC2.36(SEG20) U11.18
SEG14: IC2.37(SEG19) U11.19
SEG15: IC2.38(SEG18) U11.20
SEG16: IC2.39(SEG17) U11.21
SEG17: IC2.40(SEG16) U11.22
SEG18: IC2.41(SEG15) U11.23
SEG19: IC2.42(SEG14) U11.24
SEG20: IC2.43(SEG13) U11.25
SEG21: IC2.44(SEG12) U11.26
SEG22: IC2.45(SEG11) U11.27
SEG23: IC2.46(SEG10) U11.28
SEG24: IC2.47(SEG9) U11.29
SEG25: IC2.48(SEG8) U11.30
Sense1: P1.25 RA251.2 ; port A25
Sense2: P1.26 RA261.2 ; port A26
Speed: DA06.2 P1.6 ; port A6
SPEED1: Cm1.2 FBm1.1 IC3.5(M0C1M/IOC0_1/PU2)
SPEED2: Cm2.1 FBm2.1 IC3.6(M0C1P/PU3)
SPEED3: Cm3.1 FBm3.2 IC3.3(M0C0M/IOC0_0/PU0)
SPEED4: Cm4.2 FBm4.2 IC3.4(M0C0P/PU1)
SpeedIN: CA601.2 IC3.36(KWR3/IOC1_7/PR3) RA604.2
SPLIT: C35.1 R73.2 R78.1 U3.5(SPLIT)
TACHO1: Cz1.2 IC3.21(M3C1M/IOC1_3/PV6) Zm1.1
TACHO2: Cz2.1 IC3.22(M3C1P/PV7) Zm2.1
TACHO3: Cz3.1 IC3.19(M3C0M/IOC1_2/PV4) Zm3.2
TACHO4: Cz4.2 IC3.20(M3C0P/PV5) Zm4.2
Turn left+: DA23.1 P1.23 ; port A23
Turn right+: DA18.1 P1.18 ; port A18
vBAT_12V: C1.1 C1_1.1 Ec01.1 L1_1.1 QF1.S R2.2 Rf4.2 U1_2.4(IN) U1_2.5(EN)
X0: C10.1 IC3.72(EXTAL) OSC1.1
X1: C11.1 IC3.73(XTAL) OSC1.2
NetB1_1: B1.1(A) D10.2 RA9.1 RA10.1
NetB1_2: B1.2(B) D10.1 Q3.C
NetC2_1: C2.1 U1_1.1(BOOT)
NetC2_1_2: C2_1.2 U1_2.7(PGDL)
NetC2_2: C2.2 D3.2 L1_1.2 U1_1.10(PH)
NetC3_2_2: C3_2.2 R57.1 R58.1 U1_2.8(FB)
NetC6_2: C6.2 R3_2.2 U1_1.8(COMP)
NetC7_1_2: C7_1.2 U1_1.4(SS/TR)
NetC8_1_2: C8_1.2 R3_2.1
NetCA18_1: CA18.1 DAL18.1 RA182.2 RA183.2
NetCA23_1: CA23.1 DAL23.1 RA232.2 RA233.2
NetD1_1: D1.1 L1.1
NetD2_1: D2.1 D3_1.1 L2.1
NetD4_2: D4.2 DL2.1 DL3.1 DL6.1 DL8.1 DL10.1 DL11.1 LD2.1 LD3.1 LD13.1 LD14.1
NetD7_1: D7.1 R18.1 R19.1 R20.1 R21.1 R22.1 R23.1 R24.1 R25.1 R26.1 R27.1 R28.1 R29.1 R30.1 R31.1 R32.1 R33.1 R34.1 R35.1 R36.1 R37_1.1
NetDA03_2: DA03.2 RA131.1
NetDA05_2: DA05.2 RA051.1
NetDA06_1: DA06.1 RA601.2 RA602.1
NetDA12_1: DA12.1 RA1201.1 RA1202.2
NetDA14_1: DA14.1 RA142.1
NetDA15_2: DA15.2 RA152.1
NetDA18_2: DA18.2 RA181.1
NetDA20_2: DA20.2 RA201.1
NetDA21_2: DA21.2 RA211.1
NetDA22_2: DA22.2 RA221.2
NetDA23_2: DA23.2 RA231.1
NetDA26_2: DA26.2 RA161.2
NetDA27_1: DA27.1 RA272.2
NetDA29_2: DA29.2 DAL29.1 RA293.2 RA294.1
NetDA31_1: DA31.1 DA31_1.1 RA284_1.2
NetDA31_2: DA31.2 QA28.C
NetDA31_2_2: DA31_2.2 LDA31.1 RA283.2 RA285.1
NetDA32_1: DA32.1 RA321.2
NetDAL14_2: DAL14.2 RA141.2 RA143.1
NetDAL15_1: DAL15.1 RA151.2 RA153.1
NetDAL16_1: DAL16.1 RA162.1 RA163.2
NetDAL20_1: DAL20.1 RA202.2 RA203.1
NetDAL21_1: DAL21.1 RA212.2 RA213.1
NetDAL22_2: DAL22.2 RDX8.1
NetDAL27_2: DAL27.2 RA271.1 RA273.2
NetDAL29_2: DAL29.2 RA292.1 RA294.2
NetDAL32_2: DAL32.2 RA322.2 RA323.1
NetDL1_1: DL1.1 DL2.2
NetDL1_2: DL1.2 RL3.2
NetDL3_2: DL3.2 DL4.1
NetDL4_2: DL4.2 RL8.2
NetDL5_1: DL5.1 DL6.2
NetDL5_2: DL5.2 RL10.1
NetDL7_1: DL7.1 DL8.2
NetDL7_2: DL7.2 RL12.1
NetDL9_1: DL9.1 DL10.2
NetDL9_2: DL9.2 RL9_1.2
NetDL11_2: DL11.2 DL12.1
NetDL12_2: DL12.2 RL12_1.1
NetDL15_1: DL15.1 LD13.2
NetDL15_2: DL15.2 DL17.1
NetDL16_1: DL16.1 LD14.2
NetDL16_2: DL16.2 DL18.1
NetDL17_2: DL17.2 RL17.2
NetDL18_2: DL18.2 RL18.2
NetFBm1_2: FBm1.2 M1.1 Rm1.2
NetFBm2_2: FBm2.2 M1.2 Rm1.1
NetFBm3_1: FBm3.1 M1.3 Rm2.1
NetFBm4_1: FBm4.1 M1.4 Rm2.2
NetFBq1_2: FBq1.2 M3.1 Rq1.2
NetFBq2_2: FBq2.2 M3.2 Rq1.1
NetFBq3_1: FBq3.1 M3.3 Rq2.1
NetFBq4_1: FBq4.1 M3.4 Rq2.2
NetFBq5_2: FBq5.2 M4.1 Rq21.2
NetFBq6_2: FBq6.2 M4.2 Rq21.1
NetFBq7_1: FBq7.1 M4.3 Rq22.1
NetFBq8_1: FBq8.1 M4.4 Rq22.2
NetIC4_10: IC4.10(O7) RDX3.2
NetIC4_11: IC4.11(O6) RDX5.1
NetIC4_12: IC4.12(O5) RD14_1.1
NetIC4_13: IC4.13(O4) RDX12.1
NetIC4_14: IC4.14(O3) RDX9.2
NetIC4_15: IC4.15(O2) RDX2.2
NetIC4_16: IC4.16(O1) RDX4.1
NetIC5_10: IC5.10(O7) RDX6.1
NetIC5_11: IC5.11(O6) RD13_1.1
NetIC5_12: IC5.12(O5) RD26_2.1
NetIC5_13: IC5.13(O4) RD26_1.2
NetIC5_14: IC5.14(O3) RDX8.2
NetIC5_15: IC5.15(O2) RDX14.1
NetIC5_16: IC5.16(O1) RDX13.1
NetLC1_1: LC1.1 LC1_1.2
NetLC2_2: LC2.2 LC2_1.1
NetLCan1_1: LCan1.1 R73.1 U3.6(CANL)
NetLCan2_1: LCan2.1 R78.2 U3.7(CANH)
NetLD1_1: LD1.1 LD2.2
NetLD1_2: LD1.2 RL1.2
NetLD3_2: LD3.2 LD4.1
NetLD4_2: LD4.2 RL5.2
NetLD13_1_2: LD13_1.2 RD13_1.2
NetLD14_1_2: LD14_1.2 RD14_1.2
NetLD26_1: LD26.1 RD26_1.1
NetLD26_4: LD26.4 RD26_2.2
NetLDA03_1: LDA03.1 RA132.2 RA133.1
NetLDA05_1: LDA05.1 RA052.2 RA053_1.1
NetLDA31_2: LDA31.2 RA284.2 RA285.2
NetLDX1_2: LDX1.2 RDX1.1
NetLDX2_2: LDX2.2 RDX2.1
NetLDX3_2: LDX3.2 RDX3.1
NetLDX4_2: LDX4.2 RDX4.2
NetLDX5_2: LDX5.2 RDX5.2
NetLDX6_2: LDX6.2 RDX6.2
NetLDX7_2: LDX7.2 RDX7.2
NetLDX9_2: LDX9.2 RDX9.1
NetLDX10_2: LDX10.2 RDX10.1
NetLDX11_2: LDX11.2 RDX11.2
NetLDX12_2: LDX12.2 RDX12.2
NetLDX13_2: LDX13.2 RDX13.2
NetLDX14_2: LDX14.2 RDX14.2
NetLR1_2: LR1.2 R37.2 R38.1
NetM2_1: M2.1 Rz1.2 Zm1.2
NetM2_2: M2.2 Rz1.1 Zm2.2
NetM2_3: M2.3 Rz2.1 Zm3.1
NetM2_4: M2.4 Rz2.2 Zm4.1
NetQ3_B: Q3.B RA11.1
NetQ11_B: Q11.B RT131.2 RT141.1
NetQ11_C: Q11.C RL2.1 RL4.1 RL6.1 RL7.1 RL9.1 RL10_1.1 RL11.1 RL11_1.1 RL13.1 RL14.1
NetQA28_B: QA28.B RA281.2 RA282.2
NetQA29_1_B: QA29_1.B RA291_3.2 RA291_4.2
NetQA29_B: QA29.B RA291.2 RA291_1.2
NetQA29_C: QA29.C QA29_1.C RA292_1.2
NetQF1_G: QF1.G QXF_1.C Rf4.1
NetQX1_1_B: QX1_1.B RX1_1.2 RX1_2.1
NetQX1_1_C: QX1_1.C RDX10.2
NetQX2_1_B: QX2_1.B RX2_1.2 RX2_2.1
NetQX2_1_C: QX2_1.C RDX11.1
NetQX3_1_B: QX3_1.B RX3_1.2 RX3_2.1
NetQX3_1_C: QX3_1.C RDX7.1
NetQXF_1_B: QXF_1.B R3_1.1
NetR1_1: R1.1 R4.2 U1_1.3(EN)
NetR2_1: R2.1 R6_1.2 U1_1.7(VSENSE)
NetR36_1_2: R36_1.2 U1_1.5(RT/CLK)
NetR37_1: R37.1 R37_1.2
NetR59_1: R59.1 U1_2.6(PG)
NetR301_2: R301.2 R302.1 R303.2
NetR401_1: R401.1 R402.1 R403.2
NetRA11_2: RA11.2 RA12.1
NetRA051_2: RA051.2 RA052.1
NetRA131_2: RA131.2 RA132.1
NetRA141_1: RA141.1 RA142.2
NetRA151_1: RA151.1 RA152.2
NetRA161_1: RA161.1 RA162.2
NetRA181_2: RA181.2 RA182.1
NetRA201_2: RA201.2 RA202.1
NetRA211_2: RA211.2 RA212.1
NetRA221_1: RA221.1 RA222.2 RA223.1
NetRA231_2: RA231.2 RA232.1
NetRA271_2: RA271.2 RA272.1
NetRA284_1: RA284.1 RA284_1.1
NetRA292_2: RA292.2 RA292_1.1
NetRA321_1: RA321.1 RA322.1
NetRA602_2: RA602.2 RA603.1 RA604.1
NetRA1102_1: RA1102.1 RA1103.2 RA1104.1
NetRA1202_1: RA1202.1 RA1203.2 RA1204.1
NetRL1_1: RL1.1 RL2.2
NetRL3_1: RL3.1 RL4.2
NetRL5_1: RL5.1 RL6.2
NetRL7_2: RL7.2 RL8.1
NetRL9_1_1: RL9_1.1 RL10_1.2
NetRL9_2: RL9.2 RL10.2
NetRL11_1_2: RL11_1.2 RL12_1.2
NetRL11_2: RL11.2 RL12.2
NetRL13_2: RL13.2 RL17.1
NetRL14_2: RL14.2 RL18.1

Not connected (* = marked no-connect by the designer): IC2 10(~{RD}) 14(OSCO) 15(NC) 18(~{IRQ}) 19(BZ) 20(~{BZ}) 25(SEG31) 26(SEG30) 27(SEG29) 28(SEG28) 29(SEG27) 30(SEG26); IC3 2(NC) 23(NC) 24(NC) 44(FP7/PWM7/PP7) 45(FP8/KWT0/IOC1_4/PT0) 46(FP9/KWT1/IOC1_5/PT1) 48(FP11/KWT3/IOC1_7/PT3) 49(FP12/PR4) 51(PT4/IOC0_4/KWT4/FP13) 60(PH3/SS/SDA/FP22) 63(PH4/FP23) 64(PH5/FP24) 65(PH6/FP25) 66(PH7/FP26) 67(PR7/FP27) 68(PB0/FP28) 74(PA0/~{IRQ}/FP29) 75(PA1/~{XIRQ}/FP30) 76(PA2/FP31) 80(PA6/FP35) 82(PB1/FP37) 83(PB2/FP38) 84(PB3/FP39) 86(PB5/BP1) 87(PB6/BP2) 88(PB7/BP3); IC4 9(IN9); IC5 9(IN9); P4 3 5; U1_1 6(PWRGD); U11 32 33

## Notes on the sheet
- 车速电源输出
- 点火电源
- 蓄电池正
- 抵挡指示+
- 远光灯-
- 后雾灯+
- 右转向+
- 车速信号-
- 取力器+
- 照明输入+
- GND
- 前雾灯+
- 排气制动 预留
- 左转向+
- 充放电-
- 压力传感器1-
- 安全带未系信号-
- 门开报警-
- 燃油信号
- CANL
- CANH
- 压力传感器2-
- 货箱举升-
- 制动器故障（高悬空有效）
- ABS+
- 18-32v
- 近光灯+
- 远光+
- 制动故障-
- 驻车-
- (near QF1) GPIO
- 12V
- (near P1) AMP32接口
- 12V ת5V
- (near U1_1) Enable threshold voltage 1.15-1.25-1.36
- (near LR1) 充放电
- (near R6_1) R1=R2*(VOUT-0.8)/0.8V
- 电源模块
- (near RA163) 1k
- (near DA14) 门开-
- 远光-
- 驾驶员警告
- 发动机预热
- 发动机故障
- 制动系统故障&气压报警
- 尿素液位低
- 油水分离
- OBD
- (near RA233) 1k
- ̥ѹ
- (near IC2) 液晶驱动电路
- (near RA183) 1k
- (near RDX1) 水温
- 右转+
- 后雾
- 前雾
- 左转+
- (near DA27) 货箱举动-
- 排气高
- 空滤器堵塞
- (near RDX13) 燃油
- (near RDX14) 安全带
- (near RDX8) 排气制动(CAN&硬件)
- (near LD26) 红黄双色
- (near RD13_1) GPF再生禁止
- 机油压力
- 制动器磨损（高悬空有效）
- 制动器磨损-
- ABS（高悬空有效）
- 驻车制动-
- 转速信号-
- CAN L
- CAN驱动电路
- (near U3) 波特率=500kbps
- (near RA603) 车速信号-
- (near D22) CAN H
- (near U3) Note：
  传导电流法测CAN信号线
  CAN总线上串磁珠和并联20PF的电容
  可以降低传导电流法
- IG唤醒
- 小灯信号-
- 0欧姆代替
- (near RA1102) 贴51K
- 安全带-
- (near RA1203) 安全带信号
- 排气制动
- (near RA221) 贴51K
- 更改记录：
  1、水温报警
  2、AD采样并联1M电阻
- Labels drawn without touching a wire or pin: Exhaust brake+

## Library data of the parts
B1 = Buzzer
C0 C1 C1_1 C3_2 Cm1-Cm4 Cq1-Cq4 Cq21-Cq24 Cz1-Cz4 LC1 LC1_1 LC2 LC2_1 = CAP: Capacitor
C2 C4_1 C6 C7_1 C8_1 C301 C401 C501 CA22 CA101 CA251 CA261 CA601 CA1101 = Pro82C5.TMP_0.1uF_27
C2_1 C5 C7-C13 C33 C37-C39 C101-C103 CA18 CA23 CS1 = CAP
C3_1 = VZH220/50V
C4 Ec02 = VD220/16V
C35 = CAP: 贴片电容; Tolerance: 10%; Dielectric: X7R; Capacitance: 0.1uF; Rated Voltage: 50V
D1-D3 D3_1 D4 D7 D10 DA03 DA05 DA06 DA12 DA14 DA15 DA18 DA20-DA23 DA26 DA27 DA29 DA31 DA31_1 DA31_2 DA32 = DIODE
D21 D22 = TVS: 贴片TVS; module: CAN
DAL14 DAL32 LD1-LD4 LD13 LD14 LDA31 LDX1 LDX6 LDX14 LR1 = LED_R
DAL15 = LED_B: Blue
DAL16 DAL18 DAL23 = LED_g: Green
DAL20 DAL29 LDX2 LDX4 LDX9 LDX11 = LED_Y: Yellow
DAL21 LDA03 = LED_G: Green
DAL22 LD14_1 LDA05 LDX3 LDX7 LDX13 = LED_y: Yellow
DAL27 LD13_1 LDX5 LDX10 LDX12 = LED_r
Designator25-Designator28 = BNC: BNC Connector
DL1-DL12 DL15-DL18 = LED_W: LED
Ec01 = ELECTROLY: 220uF/25V
FBm1-FBm4 FBq1-FBq8 Zm1-Zm4 = BEAD
IC2 = HT1621
IC3 = MC9S12HY/HA-Family 100 LQFP: Freescale
IC4 IC5 = 2003
L1 L2 R1-R3 R3_1 R3_2 R4 R6_1 R18-R36 R36_1 R37 R37_1 R38 R73 RA9-RA12 RA051 RA052 RA053_1 RA131-RA133 RA141-RA143 RA151-RA153 RA161-RA163 RA181-RA183 RA201-RA203 RA211-RA213 RA231-RA233 RA271-RA273 RA281-RA284 RA284_1 RA285 RA291 RA291_1 RA291_3 RA291_4 RA292 RA292_1 RA293 RA294 RA321-RA323 RB1 RD13_1 RD14_1 RD26_1 RD26_2 RDX1-RDX14 RL1-RL9 RL9_1 RL10 RL10_1 RL11 RL11_1 RL12 RL12_1 RL13 RL14 RL17 RL18 = RES_SMD: 贴片电阻; Resistance: KΩ; Tolerance: 5%
L1_1 R6 RS1 = R
LCan1 LCan2 = INDUCTOR: Value: 22uH
LD26 = Component_1
M1-M4 = JIX1N1
OSC1 = CRYSTAL
P4 = Port3*2: Port
Q3 = NPNN: Part Field 1: BACKGROUND
Q11 QA28 QA29 QA29_1 QX1_1 QX2_1 QX3_1 QXF_1 = NPN
QF1 = MOSFET P
R57-R59 R401-R403 R505 R1301-R1304 RA221-RA223 RA601-RA604 RA1102-RA1104 RA1201-RA1204 Rf4 RT131 RT141 RX1_1 RX1_2 RX2_1 RX2_2 RX3_1 RX3_2 = RES2
R78 = RES_SMD: 贴片电阻
R301 R302 = ZS.S01_1.2/1W_15
R303 RA251 RA261 = ZB314-0D.S01_2.2k_1
Rm1 Rm2 Rq1 Rq2 Rq21 Rq22 Rz1 Rz2 = RES0603
U3 = TJA1040: CAN Interface
U11 = Component_1_1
